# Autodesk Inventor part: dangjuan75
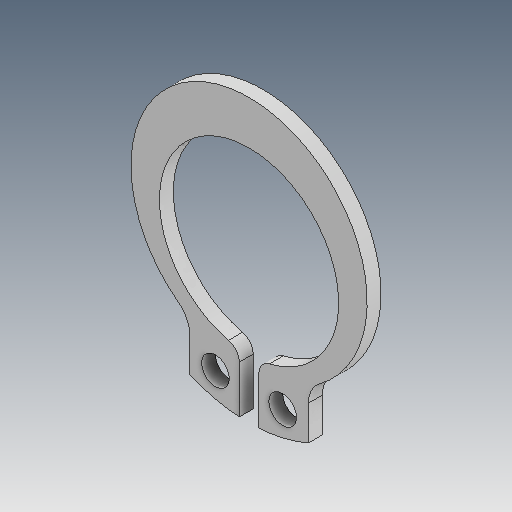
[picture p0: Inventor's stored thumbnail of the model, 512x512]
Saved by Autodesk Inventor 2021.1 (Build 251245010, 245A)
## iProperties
Created: 2018-07
Part Number: dangjuan75
Material: Ogólny
Document SubType Name: Modeling
Designer: user
Density: 1 g/cm^3
Appearance: Domyślna
Author: user
Revision Number: ÈÎºÎ
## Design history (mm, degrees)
feature "Í¹Ì¨-À­Éì1"
node "Bryła1"
